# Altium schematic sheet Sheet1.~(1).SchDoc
size A3; SheetNumber: 1; SheetTotal: 2
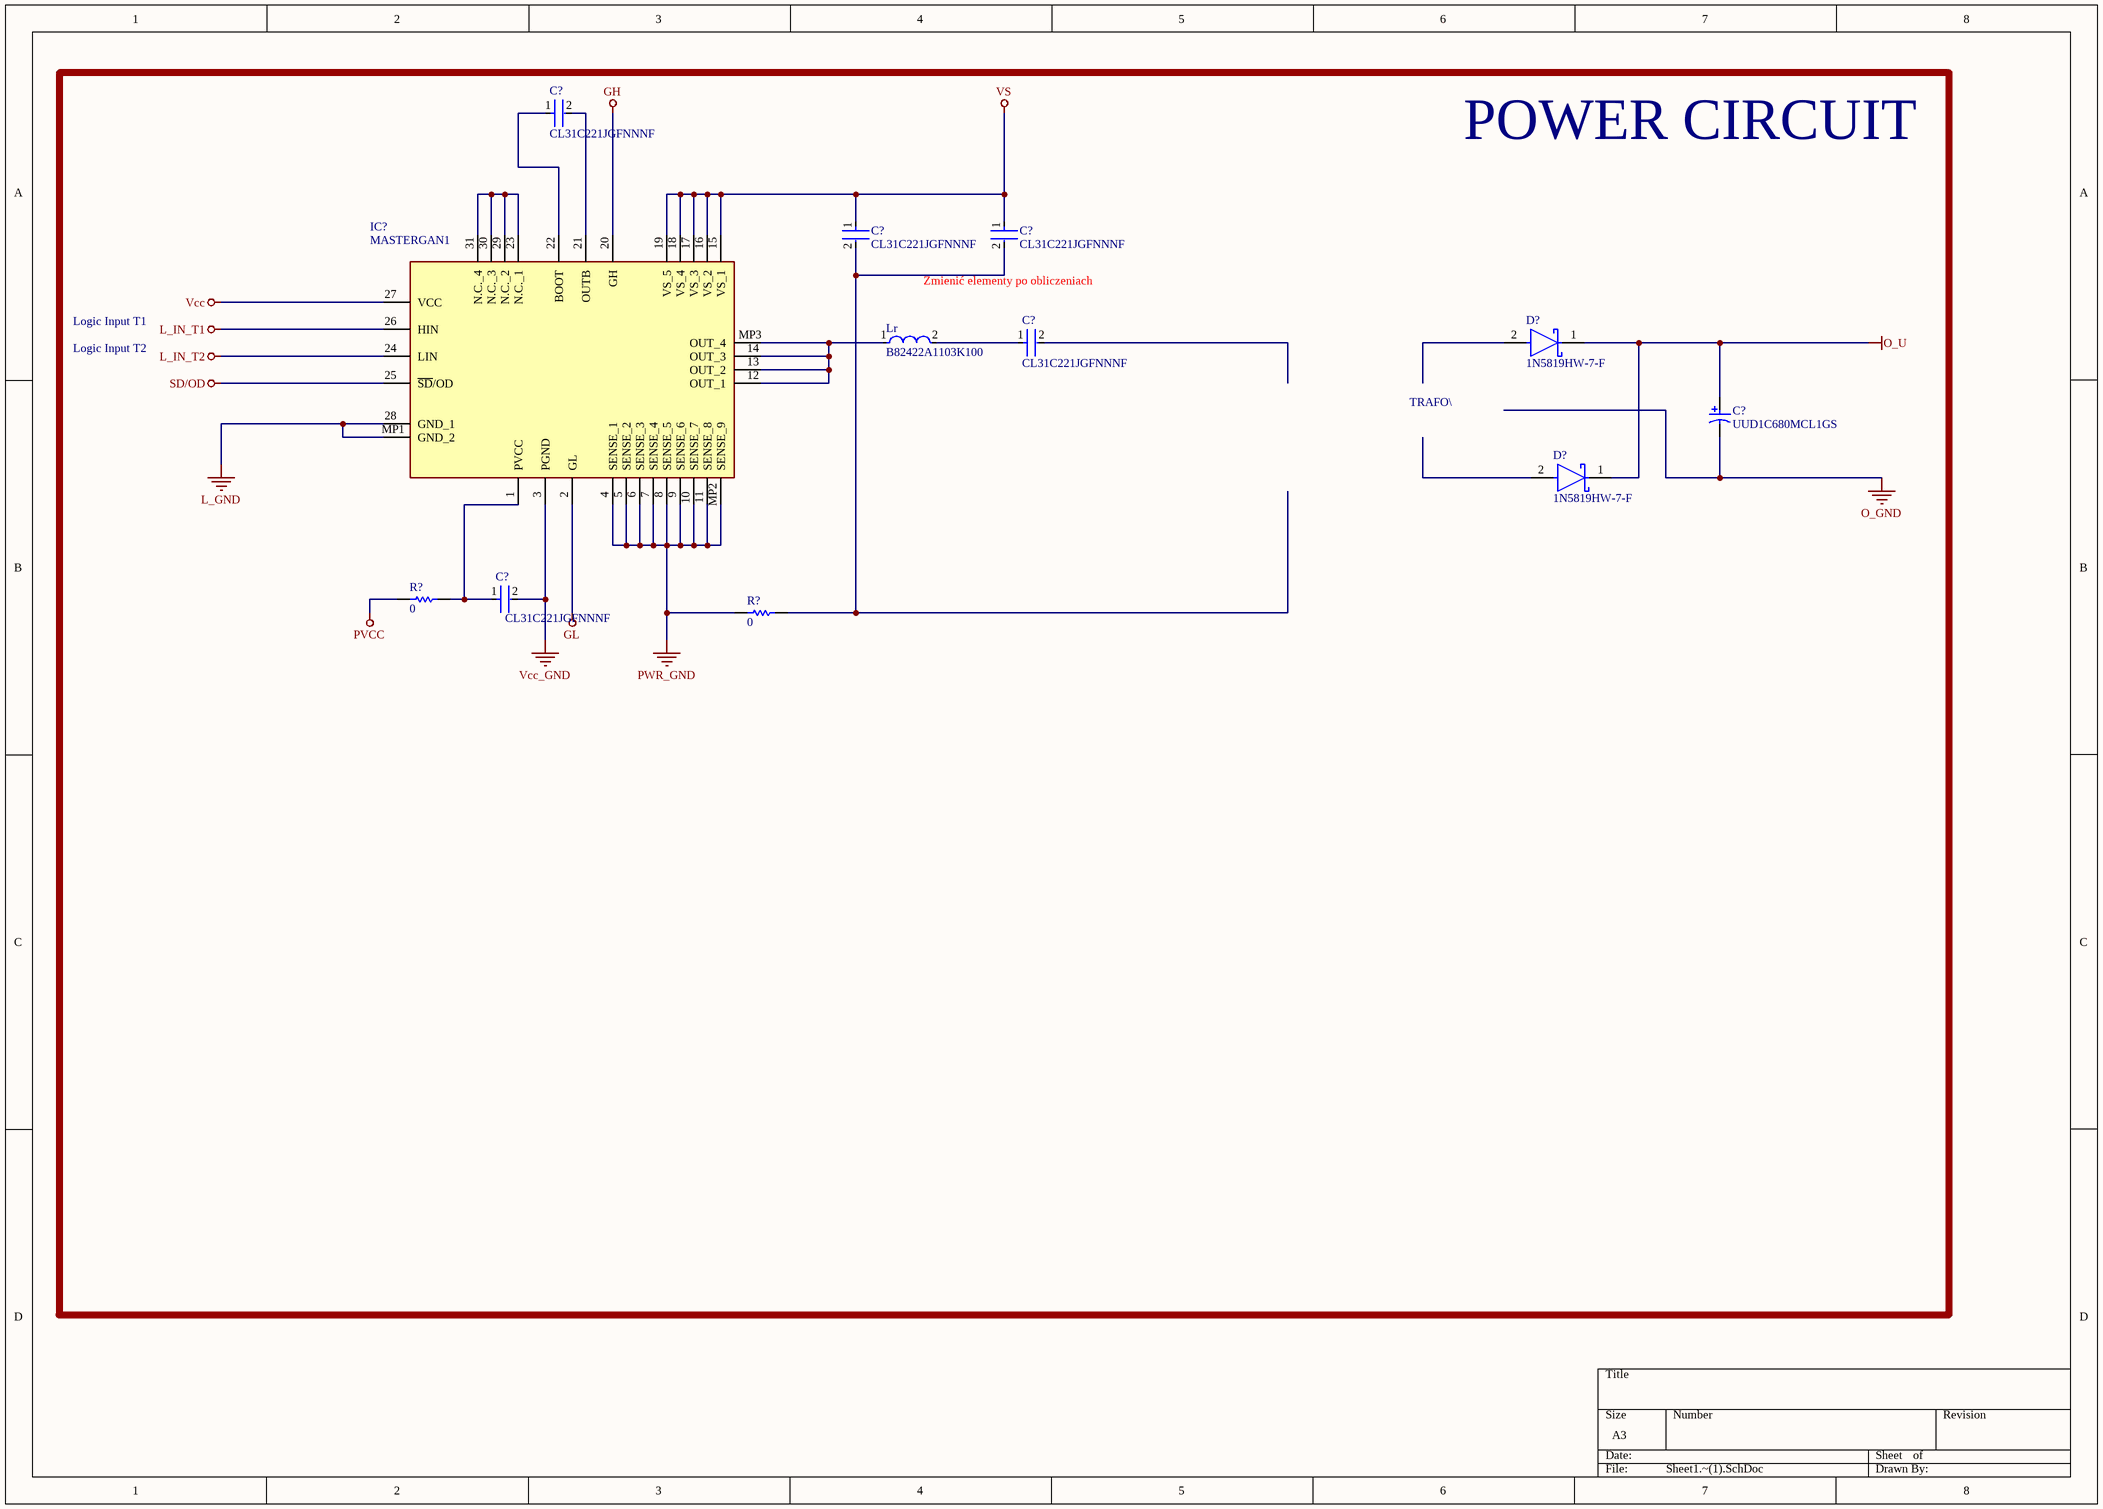
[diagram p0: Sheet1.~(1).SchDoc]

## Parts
(Parts that share a designator on the sheet are numbered #1, #2 ... from top to bottom, then left to right.)
C?#1  CL31C221JGFNNNF  [FP-CL31-IPC_C]
C?#2  CL31C221JGFNNNF  [FP-CL31-IPC_C]
C?#3  CL31C221JGFNNNF  [FP-CL31-IPC_C]
C?#4  CL31C221JGFNNNF  [FP-CL31-IPC_C]
C?#5  UUD1C680MCL1GS  [NIC-CAPA2-6.3X5.8_V]
C?#6  CL31C221JGFNNNF  [FP-CL31-IPC_C]
D?#1  1N5819HW-7-F  [FP-SOD123-IPC_A]
D?#2  1N5819HW-7-F  [FP-SOD123-IPC_A]
IC?  MASTERGAN1  [MASTERGAN1]
Lr  B82422A1103K100  [FP-B82422A-MFG]
R?#1  value 0  (hidden comment: Resistor)
R?#2  value 0  (hidden comment: Resistor)

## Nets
GH: IC?.20(GH)
GL: IC?.2(GL)
L_GND: IC?.28(GND_1) IC?.MP1(GND_2)
L_IN_T1: IC?.26(HIN)
L_IN_T2: IC?.24(LIN)
O_GND: C?#5.2
O_U: C?#5.1 D?#1.1(C) D?#2.1(C)
PVCC: R?#1.1
PWR_GND: IC?.4(SENSE_1) IC?.5(SENSE_2) IC?.6(SENSE_3) IC?.7(SENSE_4) IC?.8(SENSE_5) IC?.9(SENSE_6) IC?.10(SENSE_7) IC?.11(SENSE_8) IC?.MP2(SENSE_9) R?#2.1
SD/OD: IC?.25(~{SD}/OD)
Vcc: IC?.27(VCC)
Vcc_GND: C?#6.2 IC?.3(PGND)
VS: C?#2.1 C?#3.1 IC?.15(VS_1) IC?.16(VS_2) IC?.17(VS_3) IC?.18(VS_4) IC?.19(VS_5)
NetC?#1_1: C?#1.1 IC?.22(BOOT)
NetC?#1_2: C?#1.2 IC?.21(OUTB)
NetC?#2_2: C?#2.2 C?#3.2 R?#2.2
NetC?#4_1: C?#4.1 Lr.2
NetC?#6_1: C?#6.1 IC?.1(PVCC) R?#1.2
NetIC?_12: IC?.12(OUT_1) IC?.13(OUT_2) IC?.14(OUT_3) IC?.MP3(OUT_4) Lr.1
NetIC?_23: IC?.23(N.C._1) IC?.29(N.C._2) IC?.30(N.C._3) IC?.31(N.C._4)

Not connected (* = marked no-connect by the designer): C?#4 2; D?#1 2(A); D?#2 2(A)

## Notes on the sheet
- POWER CIRCUIT
- Zmienić elementy po obliczeniach
- Logic Input T1
- Logic Input T2
- TRAFO\

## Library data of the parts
C?#1-C?#4 C?#6 = CMP-13271-001211-1: Cap Ceramic 220pF 500V C0G ±5% SMD 1206 +125°C Embossed T/R
C?#5 = CMP-0687-00035-1: Aluminum Electrolytic Capacitor, UD Series, Low Impedance, 68 uF, 16 V, + / - 20%, -55 to 105 degC, Chip Type, 6.3 x 5.8 mm D x L, Pb-Free, Reel; Manufacturer: Nichicon; Rated Voltage: 16 V; Endurance Time: 2000 h; Rated Ripple Current (at 100kHz): 230 mA; Rated Capacitance: 68 uF; Impedance: 0.44 Ohm; Packing: Dia382mm Reel; Tolerance Rated Capacitance: -20 to 20%
D?#1 D?#2 = CMP-0303-00003-3: DIODE SCHOTTKY 40V 1A SOD123; Forward Voltage: 450mV; Capacitance: 110pF; Max Forward Surge Current (Ifsm): 25A; Peak Reverse Current: 50uA; Polarity: Standard; Element Configuration: Single; Max Power Dissipation: 450mW
IC? = CMP-020-000000-1: Integrated Circuit; Manufacturer_Name: STMicroelectronics
Lr = CMP-2000-05912-2: FIXED IND 10UH 180MA 1.6 OHM SMD; Tolerance: 10%; Core Material: Ferrite; Q Factor: 27; Self Resonant Frequency: 25MHz; Shielding: Unshielded; Test Frequency: 1MHz; Series Resistance: 1.6R
R?#1 R?#2 = Resistor: SimulationGenericComponent: True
